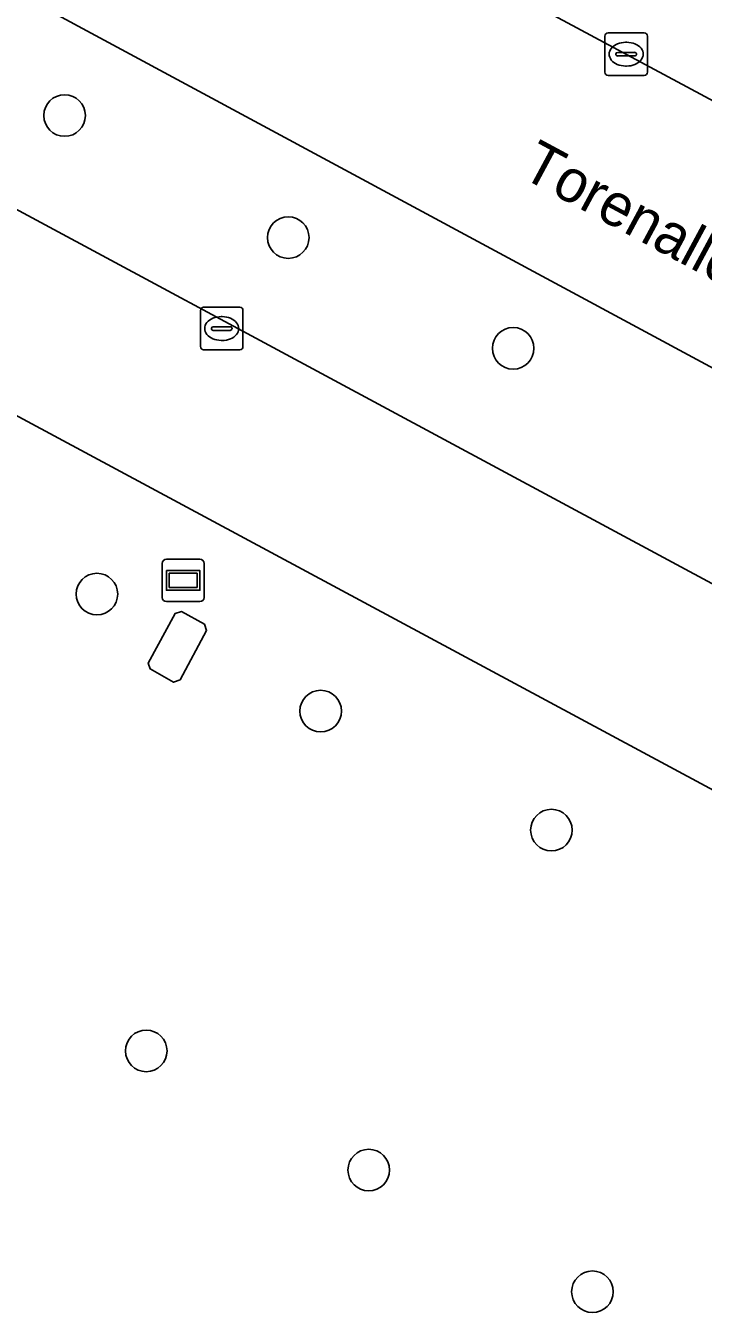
# Model space of a CAD drawing. Extents: x 159489 to 160304, y 383825 to 384531.
# Drawn here: x 159673.86 to 159689.8, y 384247.66 to 384277.95 of the extents above; entities that cross this region are included whole.
import ezdxf

# ---------------------------------------------------------------- set-up
doc = ezdxf.new("R2010")
doc.units = 0
for name, color, linetype in [('IMGEO_Boom', 7, 'Continuous'), ('IMGEO_Groenvoorziening', 7, 'Continuous'), ('IMGEO_Kolk', 7, 'Continuous'), ('IMGEO_Openbare_ruimte_label', 7, 'Continuous'), ('IMGEO_Rijbaan_lokaal_gesloten', 7, 'Continuous'), ('IMGEO_Terreindeel_open', 7, 'Continuous'), ('IMGEO_Verklikker', 7, 'Continuous'), ('IMGEO_Voetpad_gesloten', 7, 'Continuous'), ('IMGEO_Voetpad_open', 7, 'Continuous')]:
    doc.layers.add(name, color=color, linetype=linetype)

msp = doc.modelspace()

# ---------------------------------------------------------------- linework, layer by layer
at = {"layer": 'IMGEO_Boom'}
for centre in [(159674.77, 384275.837), (159680.033, 384272.965), (159685.325, 384270.361), (159675.531, 384264.58), (159680.795, 384261.827), (159686.224, 384259.028), (159676.691, 384253.835), (159681.926, 384251.031), (159687.19, 384248.17)]:
    msp.add_circle(centre, 0.489, dxfattribs=at)
at = {"layer": 'IMGEO_Groenvoorziening'}
for points in [[(159699.162, 384260.982), (159698.746, 384265.2), (159658.313, 384286.981)], [(159657.072, 384282.538), (159698.254, 384260.388)], [(159699.221, 384255.028), (159655.026, 384278.787)]]:
    msp.add_lwpolyline(points, dxfattribs=at)
msp.add_lwpolyline([(159677.491, 384262.564), (159677.334, 384262.506), (159676.783, 384262.818), (159676.738, 384262.957), (159677.369, 384264.121), (159677.521, 384264.167), (159678.06, 384263.87), (159678.11, 384263.721)], close=True, dxfattribs=at)
at = {"layer": 'IMGEO_Kolk'}
for p, q in [((159687.483, 384276.854), (159687.483, 384277.706)), ((159687.558, 384277.78), (159688.41, 384277.78)), ((159688.484, 384277.706), (159688.484, 384276.854)), ((159687.742, 384277.274), (159687.742, 384277.286)), ((159687.785, 384277.323), (159688.183, 384277.323)), ((159687.971, 384277.56), (159687.996, 384277.56)), ((159688.226, 384277.286), (159688.226, 384277.274)), ((159688.18, 384277.237), (159687.782, 384277.237)), ((159687.994, 384277), (159687.969, 384277)), ((159688.41, 384276.78), (159687.558, 384276.78)), ((159677.966, 384270.4), (159677.966, 384271.252)), ((159678.041, 384271.326), (159678.893, 384271.326)), ((159678.967, 384271.252), (159678.967, 384270.4)), ((159678.454, 384271.106), (159678.479, 384271.106)), ((159678.225, 384270.82), (159678.225, 384270.832)), ((159678.663, 384270.783), (159678.265, 384270.783)), ((159678.268, 384270.869), (159678.666, 384270.869)), ((159678.709, 384270.832), (159678.709, 384270.82)), ((159678.893, 384270.326), (159678.041, 384270.326)), ((159678.477, 384270.546), (159678.452, 384270.546))]:
    msp.add_line(p, q, dxfattribs=at)
for points in [[(159687.483, 384276.854), (159687.483, 384277.706)], [(159687.558, 384277.78), (159688.41, 384277.78)], [(159688.484, 384277.706), (159688.484, 384276.854)], [(159688.41, 384276.78), (159687.558, 384276.78)], [(159677.966, 384270.4), (159677.966, 384271.252)], [(159678.041, 384271.326), (159678.893, 384271.326)], [(159678.967, 384271.252), (159678.967, 384270.4)], [(159678.893, 384270.326), (159678.041, 384270.326)]]:
    msp.add_lwpolyline(points, dxfattribs=at)
for centre, radius, start, end in [((159687.56, 384277.704), 0.0765, 91.552, 178.448), ((159687.56, 384277.704), 0.0765, 91.552, 178.448), ((159688.408, 384277.704), 0.0765, 1.552, 88.448), ((159688.408, 384277.704), 0.0765, 1.552, 88.448), ((159687.782, 384277.283), 0.0403, 85.8775, 175.7526), ((159688.187, 384277.285), 0.0386, 1.7309, 96.639), ((159687.779, 384277.273), 0.0366, 178.938, 274.7102), ((159688.183, 384277.28), 0.043, 264.8664, 352.4533), ((159687.56, 384276.856), 0.0765, 181.552, 268.448), ((159687.56, 384276.856), 0.0765, 181.552, 268.448), ((159688.408, 384276.856), 0.0765, 271.552, 358.448), ((159688.408, 384276.856), 0.0765, 271.552, 358.448), ((159678.043, 384271.25), 0.0765, 91.552, 178.448), ((159678.043, 384271.25), 0.0765, 91.552, 178.448), ((159678.891, 384271.25), 0.0765, 1.552, 88.448), ((159678.891, 384271.25), 0.0765, 1.552, 88.448), ((159678.265, 384270.829), 0.0403, 85.8775, 175.7526), ((159678.262, 384270.819), 0.0366, 178.938, 274.7102), ((159678.666, 384270.826), 0.043, 264.8664, 352.4533), ((159678.67, 384270.831), 0.0386, 1.7309, 96.639), ((159678.043, 384270.402), 0.0765, 181.552, 268.448), ((159678.043, 384270.402), 0.0765, 181.552, 268.448), ((159678.891, 384270.402), 0.0765, 271.552, 358.448), ((159678.891, 384270.402), 0.0765, 271.552, 358.448)]:
    msp.add_arc(centre, radius, start, end, dxfattribs=at)
for centre, major_axis, ratio, start_param, end_param in [((159687.97, 384277.28), (-0.387, 0.002), 0.722429, 4.712389, 7.853982), ((159687.995, 384277.28), (-0.39, 0.002), 0.717154, 1.570796, 4.712389), ((159678.453, 384270.826), (-0.387, 0.002), 0.722429, 4.712389, 7.853982), ((159678.478, 384270.826), (-0.39, 0.002), 0.717154, 1.570796, 4.712389)]:
    msp.add_ellipse(centre, major_axis=major_axis, ratio=ratio, start_param=start_param, end_param=end_param, dxfattribs=at)
at = {"layer": 'IMGEO_Rijbaan_lokaal_gesloten'}
for points in [[(159660.257, 384289.932), (159577.41, 384334.529), (159578.411, 384329.953), (159580.7, 384328.729), (159648.201, 384292.407), (159658.313, 384286.981), (159698.746, 384265.2), (159711.716, 384258.252), (159772.562, 384225.477)], [(159773.411, 384231.328), (159761.993, 384237.492), (159761.116, 384235.868), (159732.627, 384251.248), (159717.817, 384259.189), (159718.689, 384260.816), (159703.175, 384269.135), (159702.303, 384267.507), (159697.486, 384270.09), (159698.359, 384271.717), (159675.705, 384283.863), (159661.143, 384289.584)]]:
    msp.add_lwpolyline(points, dxfattribs=at)
at = {"layer": 'IMGEO_Terreindeel_open'}
msp.add_lwpolyline([(159677.491, 384262.564), (159678.11, 384263.721), (159678.06, 384263.87), (159677.521, 384264.167), (159677.369, 384264.121), (159676.738, 384262.957), (159676.783, 384262.818), (159677.334, 384262.506)], close=True, dxfattribs=at)
at = {"layer": 'IMGEO_Verklikker'}
for p, q in [((159677.065, 384264.502), (159677.065, 384265.302)), ((159677.065, 384265.302), (159677.065, 384264.502)), ((159677.165, 384265.402), (159677.955, 384265.402)), ((159677.955, 384265.402), (159677.165, 384265.402)), ((159678.055, 384265.302), (159678.055, 384264.502)), ((159678.055, 384264.502), (159678.055, 384265.302)), ((159677.955, 384264.402), (159677.165, 384264.402)), ((159677.165, 384264.402), (159677.955, 384264.402))]:
    msp.add_line(p, q, dxfattribs=at)
for points in [[(159677.166, 384265.134), (159677.954, 384265.134), (159677.954, 384264.67), (159677.166, 384264.67), (159677.166, 384265.134)], [(159677.231, 384265.069), (159677.231, 384264.735), (159677.889, 384264.735), (159677.889, 384265.069), (159677.231, 384265.069)]]:
    msp.add_lwpolyline(points, dxfattribs=at)
for centre, start, end in [((159677.165, 384265.302), 90, 180), ((159677.165, 384265.302), 90, 180), ((159677.955, 384265.302), 0, 90), ((159677.955, 384265.302), 360, 90), ((159677.165, 384264.502), 180, 270), ((159677.165, 384264.502), 180, 270), ((159677.955, 384264.502), 270, 0), ((159677.955, 384264.502), 270, 0)]:
    msp.add_arc(centre, 0.1, start, end, dxfattribs=at)
at = {"layer": 'IMGEO_Voetpad_gesloten'}
for points in [[(159698.254, 384260.388), (159657.072, 384282.538)], [(159655.026, 384278.787), (159699.221, 384255.028)]]:
    msp.add_lwpolyline(points, dxfattribs=at)
at = {"layer": 'IMGEO_Voetpad_open'}
msp.add_lwpolyline([(159674.569, 384284.792), (159675.705, 384283.863), (159698.359, 384271.717), (159703.175, 384269.135), (159718.689, 384260.816), (159733.502, 384252.874), (159761.993, 384237.492), (159773.411, 384231.328)], dxfattribs=at)

# ---------------------------------------------------------------- texts
at = {"layer": 'IMGEO_Openbare_ruimte_label'}
msp.add_text('Torenallee', height=1, rotation=331.6915, dxfattribs=at).set_placement((159685.464, 384274.414))

doc.saveas('drawing.dxf')
